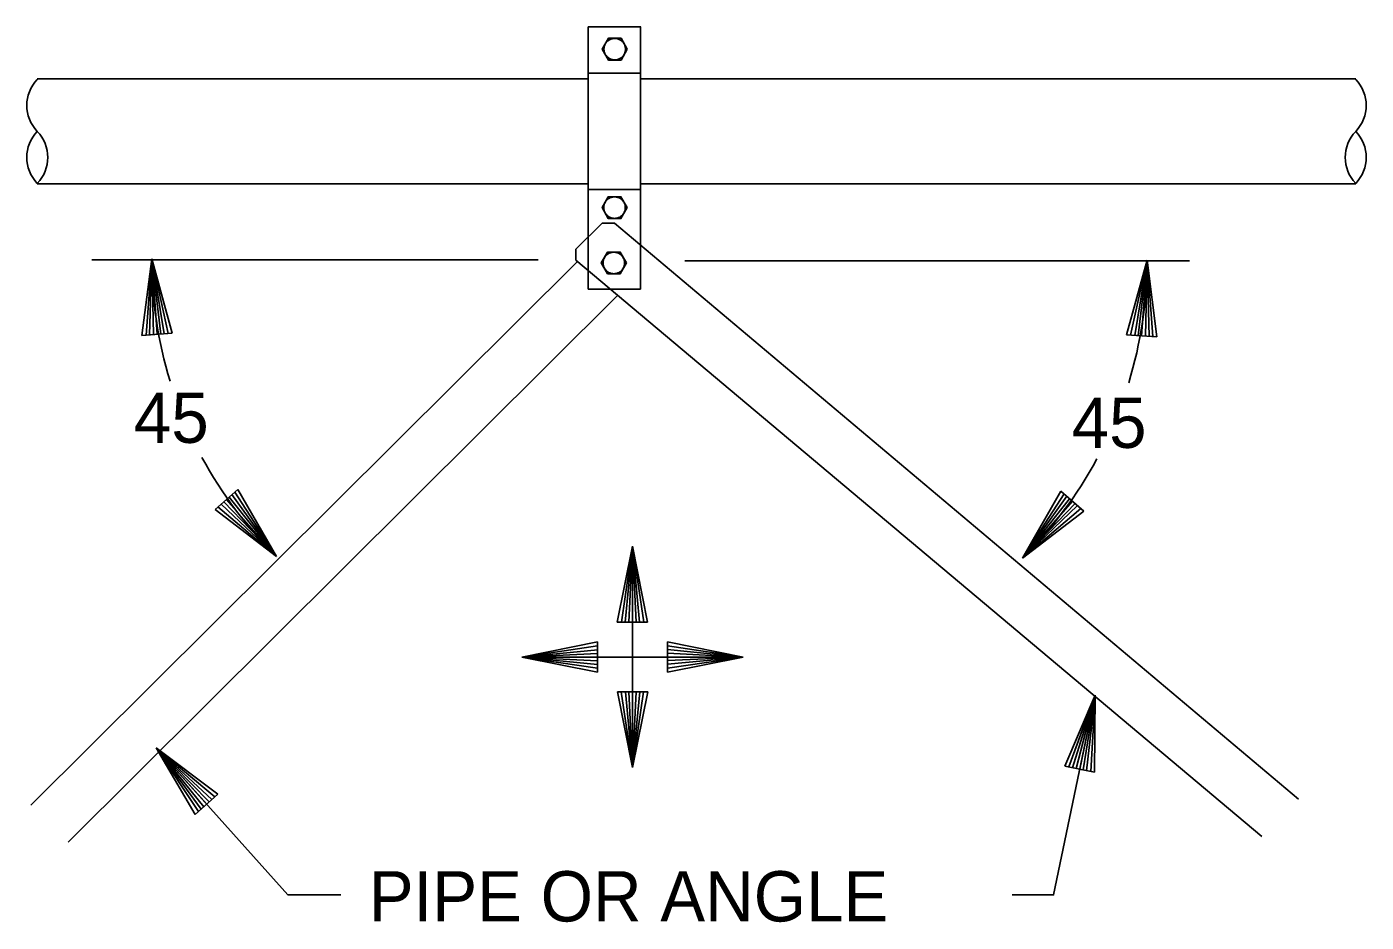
# Model space of a CAD drawing. Extents: x 10040.55 to 10045.84, y 10033.26 to 10035.76.
# Drawn here: x 10041.3043 to 10041.5706, y 10034.8582 to 10035.0362 of the extents above; entities that cross this region are included whole.
import ezdxf

# ---------------------------------------------------------------- set-up
doc = ezdxf.new("R2010")
doc.units = 0
doc.layers.add('Level 2', color=7, linetype='Continuous')

msp = doc.modelspace()

# ---------------------------------------------------------------- linework, layer by layer
at = {"layer": 'Level 2'}
for p, q in [((10041.415937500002, 10034.994427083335), (10041.415937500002, 10035.036197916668)), ((10041.426364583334, 10035.036197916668), (10041.415937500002, 10035.036197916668)), ((10041.426354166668, 10034.992781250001), (10041.426354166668, 10035.036197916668)), ((10041.415947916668, 10035.026968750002), (10041.426385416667, 10035.026968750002)), ((10041.421052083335, 10035.026979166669), (10041.421052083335, 10035.026979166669)), ((10041.306406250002, 10035.025843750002), (10041.415937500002, 10035.025843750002)), ((10041.426354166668, 10035.025843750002), (10041.568520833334, 10035.025843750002)), ((10041.306406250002, 10035.005010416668), (10041.415937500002, 10035.005010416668)), ((10041.415947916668, 10035.003875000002), (10041.426385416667, 10035.003875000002)), ((10041.426354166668, 10035.005010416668), (10041.568520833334, 10035.005010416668)), ((10041.413479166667, 10034.991979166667), (10041.418677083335, 10034.997156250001)), ((10041.418677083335, 10034.997156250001), (10041.42115625, 10034.997156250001)), ((10041.42115625, 10034.997156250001), (10041.557125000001, 10034.882687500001)), ((10041.415937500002, 10034.984062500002), (10041.415937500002, 10034.994427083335)), ((10041.413479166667, 10034.989833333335), (10041.413479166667, 10034.991979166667)), ((10041.426354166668, 10034.984062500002), (10041.426354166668, 10034.992781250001)), ((10041.4138125, 10034.9895625), (10041.305135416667, 10034.881479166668)), ((10041.406, 10034.989875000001), (10041.317260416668, 10034.989875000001)), ((10041.327197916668, 10034.974875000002), (10041.329166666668, 10034.990104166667)), ((10041.329166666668, 10034.990104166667), (10041.328020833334, 10034.974937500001)), ((10041.329166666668, 10034.990104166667), (10041.328739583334, 10034.97496875)), ((10041.330239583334, 10034.975083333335), (10041.329166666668, 10034.990104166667)), ((10041.333218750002, 10034.975302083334), (10041.329166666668, 10034.990104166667)), ((10041.329166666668, 10034.990104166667), (10041.331614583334, 10034.975166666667)), ((10041.329166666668, 10034.990104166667), (10041.329489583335, 10034.975031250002)), ((10041.329166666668, 10034.990104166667), (10041.330947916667, 10034.975135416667)), ((10041.329166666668, 10034.990104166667), (10041.332447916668, 10034.975239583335)), ((10041.413479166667, 10034.989833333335), (10041.549822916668, 10034.875302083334)), ((10041.435145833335, 10034.989656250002), (10041.535447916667, 10034.989656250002)), ((10041.522979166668, 10034.974989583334), (10041.527031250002, 10034.989791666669)), ((10041.527031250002, 10034.989791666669), (10041.523750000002, 10034.974927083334)), ((10041.527031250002, 10034.989791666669), (10041.524583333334, 10034.974854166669)), ((10041.527031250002, 10034.989791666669), (10041.52525, 10034.974822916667)), ((10041.525958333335, 10034.974770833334), (10041.527031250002, 10034.989791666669)), ((10041.527031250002, 10034.989791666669), (10041.526708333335, 10034.974718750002)), ((10041.529, 10034.974562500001), (10041.527031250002, 10034.989791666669)), ((10041.527031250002, 10034.989791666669), (10041.527458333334, 10034.97465625)), ((10041.527031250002, 10034.989791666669), (10041.528177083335, 10034.974625)), ((10041.415937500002, 10034.984062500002), (10041.426354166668, 10034.984062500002)), ((10041.4218125, 10034.982833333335), (10041.312541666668, 10034.874145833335)), ((10041.333218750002, 10034.975302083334), (10041.327197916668, 10034.974875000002)), ((10041.522979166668, 10034.974989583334), (10041.529, 10034.974562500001)), ((10041.341760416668, 10034.940270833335), (10041.346302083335, 10034.944229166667)), ((10041.346302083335, 10034.944229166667), (10041.353947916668, 10034.930927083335)), ((10041.509895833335, 10034.943916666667), (10041.502250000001, 10034.930614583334)), ((10041.514437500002, 10034.939958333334), (10041.509895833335, 10034.943916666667)), ((10041.353947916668, 10034.930927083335), (10041.342958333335, 10034.94134375)), ((10041.353947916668, 10034.930927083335), (10041.343468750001, 10034.941760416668)), ((10041.343989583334, 10034.942229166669), (10041.353947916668, 10034.930927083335)), ((10041.353947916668, 10034.930927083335), (10041.344572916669, 10034.942729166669)), ((10041.353947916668, 10034.930927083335), (10041.345114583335, 10034.943229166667)), ((10041.353947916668, 10034.930927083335), (10041.345666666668, 10034.943687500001)), ((10041.502250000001, 10034.930614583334), (10041.510531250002, 10034.943375)), ((10041.502250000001, 10034.930614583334), (10041.511083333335, 10034.942916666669)), ((10041.502250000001, 10034.930614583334), (10041.511625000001, 10034.942416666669)), ((10041.512208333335, 10034.941916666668), (10041.502250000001, 10034.930614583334)), ((10041.502250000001, 10034.930614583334), (10041.512729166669, 10034.941447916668)), ((10041.341760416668, 10034.940270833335), (10041.353947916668, 10034.930927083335)), ((10041.353947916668, 10034.930927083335), (10041.342333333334, 10034.940770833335)), ((10041.502250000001, 10034.930614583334), (10041.513239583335, 10034.941031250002)), ((10041.502250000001, 10034.930614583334), (10041.513864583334, 10034.940458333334)), ((10041.514437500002, 10034.939958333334), (10041.502250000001, 10034.930614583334)), ((10041.421718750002, 10034.91790625), (10041.424739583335, 10034.932947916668)), ((10041.424739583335, 10034.932947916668), (10041.422531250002, 10034.917895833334)), ((10041.424739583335, 10034.932947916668), (10041.423260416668, 10034.917885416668)), ((10041.424739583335, 10034.932947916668), (10041.424, 10034.917895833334)), ((10041.424739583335, 10034.888958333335), (10041.424739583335, 10034.932947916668)), ((10041.424760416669, 10034.917885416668), (10041.424739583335, 10034.932947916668)), ((10041.427739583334, 10034.917895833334), (10041.424739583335, 10034.932947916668)), ((10041.424739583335, 10034.932947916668), (10041.426135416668, 10034.917875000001)), ((10041.424739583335, 10034.932947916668), (10041.425458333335, 10034.917895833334)), ((10041.424739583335, 10034.932947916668), (10041.426979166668, 10034.917895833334)), ((10041.427739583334, 10034.917895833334), (10041.421718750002, 10034.91790625)), ((10041.417802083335, 10034.913947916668), (10041.402750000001, 10034.910947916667)), ((10041.402750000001, 10034.910947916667), (10041.417802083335, 10034.913187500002)), ((10041.402750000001, 10034.910947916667), (10041.417822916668, 10034.912343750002)), ((10041.417802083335, 10034.913947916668), (10041.417791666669, 10034.907927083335)), ((10041.446739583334, 10034.910947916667), (10041.431677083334, 10034.912427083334)), ((10041.4316875, 10034.907947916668), (10041.431697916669, 10034.913968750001)), ((10041.446739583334, 10034.910947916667), (10041.4316875, 10034.91315625)), ((10041.431697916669, 10034.913968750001), (10041.446739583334, 10034.910947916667)), ((10041.402750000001, 10034.910947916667), (10041.417802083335, 10034.911666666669)), ((10041.417812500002, 10034.91096875), (10041.402750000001, 10034.910947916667)), ((10041.402750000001, 10034.910947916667), (10041.446739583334, 10034.910947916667)), ((10041.417791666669, 10034.907927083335), (10041.402750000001, 10034.910947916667)), ((10041.402750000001, 10034.910947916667), (10041.417812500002, 10034.909468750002)), ((10041.402750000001, 10034.910947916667), (10041.417802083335, 10034.908739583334)), ((10041.402750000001, 10034.910947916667), (10041.417802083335, 10034.910208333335)), ((10041.446739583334, 10034.910947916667), (10041.431666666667, 10034.909552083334)), ((10041.431677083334, 10034.910927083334), (10041.446739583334, 10034.910947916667)), ((10041.446739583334, 10034.910947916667), (10041.4316875, 10034.911687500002)), ((10041.4316875, 10034.907947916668), (10041.446739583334, 10034.910947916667)), ((10041.446739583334, 10034.910947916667), (10041.4316875, 10034.910229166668)), ((10041.446739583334, 10034.910947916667), (10041.4316875, 10034.908708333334)), ((10041.421739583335, 10034.904010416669), (10041.427760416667, 10034.904)), ((10041.421739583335, 10034.904010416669), (10041.424739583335, 10034.888958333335)), ((10041.424739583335, 10034.888958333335), (10041.4225, 10034.904010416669)), ((10041.424739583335, 10034.888958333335), (10041.42334375, 10034.904031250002)), ((10041.424739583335, 10034.888958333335), (10041.424020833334, 10034.904010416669)), ((10041.42471875, 10034.904020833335), (10041.424739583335, 10034.888958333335)), ((10041.424739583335, 10034.888958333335), (10041.42621875, 10034.904020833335)), ((10041.424739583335, 10034.888958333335), (10041.426947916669, 10034.904010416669)), ((10041.424739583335, 10034.888958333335), (10041.425479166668, 10034.904010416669)), ((10041.427760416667, 10034.904), (10041.424739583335, 10034.888958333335)), ((10041.510687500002, 10034.889281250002), (10041.516697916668, 10034.903395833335)), ((10041.516697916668, 10034.903395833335), (10041.511479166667, 10034.889104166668)), ((10041.516697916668, 10034.903395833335), (10041.5121875, 10034.888947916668)), ((10041.516697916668, 10034.903395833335), (10041.512927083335, 10034.888802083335)), ((10041.513656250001, 10034.888635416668), (10041.516697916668, 10034.903395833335)), ((10041.516697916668, 10034.903395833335), (10041.514354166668, 10034.888510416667)), ((10041.516697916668, 10034.903395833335), (10041.515000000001, 10034.888354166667)), ((10041.516697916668, 10034.903395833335), (10041.515833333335, 10034.888197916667)), ((10041.516583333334, 10034.888041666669), (10041.516697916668, 10034.903395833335)), ((10041.340093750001, 10034.881697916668), (10041.330010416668, 10034.892895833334)), ((10041.337812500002, 10034.879677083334), (10041.330010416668, 10034.892895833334)), ((10041.342302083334, 10034.883697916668), (10041.330010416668, 10034.892895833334)), ((10041.330010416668, 10034.892895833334), (10041.338968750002, 10034.880697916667)), ((10041.330010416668, 10034.892895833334), (10041.341114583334, 10034.882604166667)), ((10041.330010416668, 10034.892895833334), (10041.338427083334, 10034.88021875)), ((10041.330010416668, 10034.892895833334), (10041.339520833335, 10034.881197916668)), ((10041.330010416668, 10034.892895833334), (10041.340604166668, 10034.882177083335)), ((10041.330010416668, 10034.892895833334), (10041.341729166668, 10034.883187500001)), ((10041.516583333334, 10034.888041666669), (10041.510687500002, 10034.889281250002)), ((10041.342302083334, 10034.883697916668), (10041.337812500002, 10034.879677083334))]:
    msp.add_line(p, q, dxfattribs=at)
for points in [[(10041.423708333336, 10035.031760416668), (10041.422458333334, 10035.029593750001), (10041.419958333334, 10035.029593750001), (10041.418708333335, 10035.031760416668), (10041.419958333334, 10035.033927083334), (10041.422458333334, 10035.033927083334)], [(10041.42334375, 10035.031760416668), (10041.42334375, 10035.031625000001), (10041.423333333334, 10035.031489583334), (10041.423312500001, 10035.031354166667), (10041.423281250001, 10035.031229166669), (10041.423239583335, 10035.031093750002), (10041.423197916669, 10035.030968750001), (10041.423145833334, 10035.03084375), (10041.423083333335, 10035.030729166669), (10041.423010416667, 10035.030614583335), (10041.422937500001, 10035.0305), (10041.422854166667, 10035.030395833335), (10041.422770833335, 10035.030291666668), (10041.422677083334, 10035.030197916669), (10041.422572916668, 10035.030104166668), (10041.422468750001, 10035.030031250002), (10041.422354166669, 10035.029947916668), (10041.422239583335, 10035.029885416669), (10041.422114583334, 10035.029822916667), (10041.421989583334, 10035.029770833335), (10041.421864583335, 10035.029718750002), (10041.421739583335, 10035.029687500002), (10041.421604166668, 10035.02965625), (10041.421479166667, 10035.029635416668), (10041.421343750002, 10035.029625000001), (10041.421208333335, 10035.029614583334), (10041.421072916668, 10035.029625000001), (10041.420937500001, 10035.029635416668), (10041.420802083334, 10035.02965625), (10041.420677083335, 10035.029687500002), (10041.420541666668, 10035.029718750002), (10041.420416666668, 10035.029770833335), (10041.420291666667, 10035.029822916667), (10041.420177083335, 10035.029885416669), (10041.420062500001, 10035.029947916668), (10041.419947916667, 10035.030031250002), (10041.419843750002, 10035.030104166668), (10041.419739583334, 10035.030197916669), (10041.419645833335, 10035.030291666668), (10041.419552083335, 10035.030395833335), (10041.419468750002, 10035.0305), (10041.419395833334, 10035.030614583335), (10041.419333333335, 10035.030729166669), (10041.419270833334, 10035.03084375), (10041.419218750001, 10035.030968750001), (10041.419166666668, 10035.031093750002), (10041.419135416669, 10035.031229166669), (10041.419104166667, 10035.031354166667), (10041.419083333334, 10035.031489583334), (10041.419072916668, 10035.031625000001), (10041.419062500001, 10035.031760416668), (10041.419072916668, 10035.031895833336), (10041.419083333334, 10035.03203125), (10041.419104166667, 10035.032156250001), (10041.419135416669, 10035.032291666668), (10041.419166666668, 10035.032416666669), (10041.419218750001, 10035.032552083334), (10041.419270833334, 10035.032666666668), (10041.419333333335, 10035.032791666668), (10041.419395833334, 10035.03290625), (10041.419468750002, 10035.033020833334), (10041.419552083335, 10035.033125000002), (10041.419645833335, 10035.033229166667), (10041.419739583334, 10035.033322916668), (10041.419843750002, 10035.03340625), (10041.419947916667, 10035.033489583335), (10041.420062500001, 10035.0335625), (10041.420177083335, 10035.033635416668), (10041.420291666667, 10035.033697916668), (10041.420416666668, 10035.03375), (10041.420541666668, 10035.033791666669), (10041.420677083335, 10035.033833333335), (10041.420802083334, 10035.033864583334), (10041.420937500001, 10035.033885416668), (10041.421072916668, 10035.033895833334), (10041.421208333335, 10035.033895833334), (10041.421343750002, 10035.033895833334), (10041.421479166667, 10035.033885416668), (10041.421604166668, 10035.033864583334), (10041.421739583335, 10035.033833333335), (10041.421864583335, 10035.033791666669), (10041.421989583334, 10035.03375), (10041.422114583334, 10035.033697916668), (10041.422239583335, 10035.033635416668), (10041.422354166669, 10035.0335625), (10041.422468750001, 10035.033489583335), (10041.422572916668, 10035.03340625), (10041.422677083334, 10035.033322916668), (10041.422770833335, 10035.033229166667), (10041.422854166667, 10035.033125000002), (10041.422937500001, 10035.033020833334), (10041.423010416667, 10035.03290625), (10041.423083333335, 10035.032791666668), (10041.423145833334, 10035.032666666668), (10041.423197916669, 10035.032552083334), (10041.423239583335, 10035.032416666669), (10041.423281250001, 10035.032291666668), (10041.423312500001, 10035.032156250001), (10041.423333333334, 10035.03203125)], [(10041.423677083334, 10035.000260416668), (10041.422427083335, 10034.99809375), (10041.419927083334, 10034.99809375), (10041.418677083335, 10035.000260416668), (10041.419927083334, 10035.002427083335), (10041.422427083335, 10035.002427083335)], [(10041.423312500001, 10035.000260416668), (10041.423312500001, 10035.000125), (10041.423302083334, 10035.000000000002), (10041.423281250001, 10034.999864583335), (10041.423250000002, 10034.999729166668), (10041.423208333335, 10034.999604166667), (10041.423166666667, 10034.999479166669), (10041.423114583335, 10034.999354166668), (10041.423052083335, 10034.999229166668), (10041.422979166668, 10034.999114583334), (10041.422906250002, 10034.999000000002), (10041.422822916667, 10034.998895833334), (10041.422739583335, 10034.998802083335), (10041.422645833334, 10034.998697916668), (10041.422541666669, 10034.998614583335), (10041.422437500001, 10034.998531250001), (10041.422322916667, 10034.998458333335), (10041.422208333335, 10034.998385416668), (10041.422083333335, 10034.998322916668), (10041.421958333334, 10034.998270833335), (10041.421833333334, 10034.998229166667), (10041.421708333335, 10034.998187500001), (10041.421572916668, 10034.998156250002), (10041.421447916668, 10034.998135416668), (10041.4213125, 10034.998125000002), (10041.421177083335, 10034.998125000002), (10041.421041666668, 10034.998125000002), (10041.420906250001, 10034.998135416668), (10041.420770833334, 10034.998156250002), (10041.420645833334, 10034.998187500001), (10041.420510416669, 10034.998229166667), (10041.420385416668, 10034.998270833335), (10041.420260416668, 10034.998322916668), (10041.420145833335, 10034.998385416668), (10041.420031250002, 10034.998458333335), (10041.419916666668, 10034.998531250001), (10041.419812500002, 10034.998614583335), (10041.419708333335, 10034.998697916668), (10041.419614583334, 10034.998802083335), (10041.419520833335, 10034.998895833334), (10041.4194375, 10034.999000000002), (10041.419364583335, 10034.999114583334), (10041.419302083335, 10034.999229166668), (10041.419239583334, 10034.999354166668), (10041.419187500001, 10034.999479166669), (10041.419135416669, 10034.999604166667), (10041.419104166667, 10034.999729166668), (10041.419072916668, 10034.999864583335), (10041.419052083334, 10035.000000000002), (10041.419041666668, 10035.000125), (10041.419031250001, 10035.000260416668), (10041.419041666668, 10035.000395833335), (10041.419052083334, 10035.000531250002), (10041.419072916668, 10035.000666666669), (10041.419104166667, 10035.000791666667), (10041.419135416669, 10035.000927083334), (10041.419187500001, 10035.001052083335), (10041.419239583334, 10035.001177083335), (10041.419302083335, 10035.001291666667), (10041.419364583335, 10035.001406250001), (10041.4194375, 10035.001520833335), (10041.419520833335, 10035.001625), (10041.419614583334, 10035.001729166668), (10041.419708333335, 10035.001822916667), (10041.419812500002, 10035.001916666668), (10041.419916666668, 10035.002), (10041.420031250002, 10035.002072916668), (10041.420145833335, 10035.002135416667), (10041.420260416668, 10035.002197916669), (10041.420385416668, 10035.002250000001), (10041.420510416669, 10035.002302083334), (10041.420645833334, 10035.002333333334), (10041.420770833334, 10035.002364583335), (10041.420906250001, 10035.002385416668), (10041.421041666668, 10035.002406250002), (10041.421177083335, 10035.002406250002), (10041.4213125, 10035.002406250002), (10041.421447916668, 10035.002385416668), (10041.421572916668, 10035.002364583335), (10041.421708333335, 10035.002333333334), (10041.421833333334, 10035.002302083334), (10041.421958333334, 10035.002250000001), (10041.422083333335, 10035.002197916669), (10041.422208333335, 10035.002135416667), (10041.422322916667, 10035.002072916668), (10041.422437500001, 10035.002), (10041.422541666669, 10035.001916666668), (10041.422645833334, 10035.001822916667), (10041.422739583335, 10035.001729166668), (10041.422822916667, 10035.001625), (10041.422906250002, 10035.001520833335), (10041.422979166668, 10035.001406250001), (10041.423052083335, 10035.001291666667), (10041.423114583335, 10035.001177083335), (10041.423166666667, 10035.001052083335), (10041.423208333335, 10035.000927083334), (10041.423250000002, 10035.000791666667), (10041.423281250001, 10035.000666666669), (10041.423302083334, 10035.000531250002)], [(10041.423541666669, 10034.989270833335), (10041.422291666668, 10034.987104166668), (10041.419791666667, 10034.987104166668), (10041.418541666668, 10034.989270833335), (10041.419791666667, 10034.991427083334), (10041.422291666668, 10034.991427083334)], [(10041.423177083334, 10034.989270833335), (10041.423177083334, 10034.989135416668), (10041.42315625, 10034.989000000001), (10041.423135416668, 10034.988864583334), (10041.423114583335, 10034.988729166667), (10041.423072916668, 10034.988604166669), (10041.423031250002, 10034.988479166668), (10041.422979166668, 10034.988354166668), (10041.422916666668, 10034.988229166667), (10041.42284375, 10034.988114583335), (10041.422770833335, 10034.988010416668), (10041.4226875, 10034.987895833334), (10041.422593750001, 10034.987802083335), (10041.4225, 10034.987708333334), (10041.422406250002, 10034.987614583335), (10041.422291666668, 10034.98753125), (10041.422187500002, 10034.987458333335), (10041.422072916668, 10034.987385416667), (10041.421947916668, 10034.987322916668), (10041.421822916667, 10034.987270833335), (10041.421697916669, 10034.987229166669), (10041.421572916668, 10034.9871875), (10041.421437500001, 10034.987166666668), (10041.421302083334, 10034.987145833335), (10041.421166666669, 10034.987125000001), (10041.421041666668, 10034.987125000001), (10041.420906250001, 10034.987125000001), (10041.420770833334, 10034.987145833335), (10041.420635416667, 10034.987166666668), (10041.420500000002, 10034.9871875), (10041.420375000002, 10034.987229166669), (10041.420250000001, 10034.987270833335), (10041.420125, 10034.987322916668), (10041.420000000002, 10034.987385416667), (10041.419885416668, 10034.987458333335), (10041.41978125, 10034.98753125), (10041.419666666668, 10034.987614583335), (10041.419572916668, 10034.987708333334), (10041.419479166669, 10034.987802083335), (10041.419385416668, 10034.987895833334), (10041.419302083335, 10034.988010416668), (10041.419229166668, 10034.988114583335), (10041.419156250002, 10034.988229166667), (10041.41909375, 10034.988354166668), (10041.419041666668, 10034.988479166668), (10041.419000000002, 10034.988604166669), (10041.418958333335, 10034.988729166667), (10041.4189375, 10034.988864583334), (10041.418916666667, 10034.989000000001), (10041.418895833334, 10034.989135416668), (10041.418895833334, 10034.989270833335), (10041.418895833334, 10034.989395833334), (10041.418916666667, 10034.989531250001), (10041.4189375, 10034.989666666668), (10041.418958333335, 10034.989802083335), (10041.419000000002, 10034.989927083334), (10041.419041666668, 10034.990052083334), (10041.41909375, 10034.990177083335), (10041.419156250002, 10034.990302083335), (10041.419229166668, 10034.990416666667), (10041.419302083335, 10034.990520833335), (10041.419385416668, 10034.990635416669), (10041.419479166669, 10034.990729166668), (10041.419572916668, 10034.990822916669), (10041.419666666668, 10034.990916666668), (10041.41978125, 10034.991000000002), (10041.419885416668, 10034.991072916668), (10041.420000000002, 10034.991145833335), (10041.420125, 10034.991208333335), (10041.420250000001, 10034.991260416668), (10041.420375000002, 10034.991302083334), (10041.420500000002, 10034.991343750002), (10041.420635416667, 10034.991364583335), (10041.420770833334, 10034.991385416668), (10041.420906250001, 10034.991406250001), (10041.421041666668, 10034.991406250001), (10041.421166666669, 10034.991406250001), (10041.421302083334, 10034.991385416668), (10041.421437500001, 10034.991364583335), (10041.421572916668, 10034.991343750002), (10041.421697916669, 10034.991302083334), (10041.421822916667, 10034.991260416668), (10041.421947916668, 10034.991208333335), (10041.422072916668, 10034.991145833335), (10041.422187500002, 10034.991072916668), (10041.422291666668, 10034.991000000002), (10041.422406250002, 10034.990916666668), (10041.4225, 10034.990822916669), (10041.422593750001, 10034.990729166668), (10041.4226875, 10034.990635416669), (10041.422770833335, 10034.990520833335), (10041.42284375, 10034.990416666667), (10041.422916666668, 10034.990302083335), (10041.422979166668, 10034.990177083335), (10041.423031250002, 10034.990052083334), (10041.423072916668, 10034.989927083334), (10041.423114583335, 10034.989802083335), (10041.423135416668, 10034.989666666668), (10041.42315625, 10034.989531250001)]]:
    msp.add_lwpolyline(points, close=True, dxfattribs=at)
for points in [[(10041.500208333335, 10034.863656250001), (10041.508458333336, 10034.863656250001), (10041.516697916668, 10034.903395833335)], [(10041.366750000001, 10034.863656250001), (10041.35625, 10034.863656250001), (10041.330010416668, 10034.892895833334)]]:
    msp.add_lwpolyline(points, dxfattribs=at)
for centre, radius, start, end in [((10041.31174494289, 10035.0205631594), 0.007424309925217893, 135.97880833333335, 224.0225027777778), ((10041.563182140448, 10035.0205631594), 0.007424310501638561, 315.9774972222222, 44.021191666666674), ((10041.31174494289, 10035.010244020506), 0.007424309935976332, 135.97749722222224, 224.02119166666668), ((10041.301067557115, 10035.010244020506), 0.007424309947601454, 315.97880833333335, 44.02250277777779), ((10041.573859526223, 10035.010244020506), 0.007424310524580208, 135.97749722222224, 224.02119166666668), ((10041.563182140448, 10035.010244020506), 0.007424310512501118, 315.97880833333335, 44.02250277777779), ((10041.412220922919, 10034.990099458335), 0.08305132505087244, 180, 197.02995555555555), ((10041.443976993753, 10034.989786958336), 0.08305132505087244, 342.97004444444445, 0), ((10041.412220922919, 10034.990099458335), 0.08305132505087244, 208.38075833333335, 225.43875000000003), ((10041.443976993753, 10034.989786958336), 0.08305132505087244, 314.56125000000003, 331.6192416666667)]:
    msp.add_arc(centre, radius, start, end, dxfattribs=at)

# ---------------------------------------------------------------- texts
for s, p in [('45', (10041.325614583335, 10034.953510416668)), ('45', (10041.512052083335, 10034.952510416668)), ('PIPE OR ANGLE', (10041.372302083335, 10034.858385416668))]:
    msp.add_text(s, height=0.010000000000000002, dxfattribs=at).set_placement(p)

doc.saveas('drawing.dxf')
